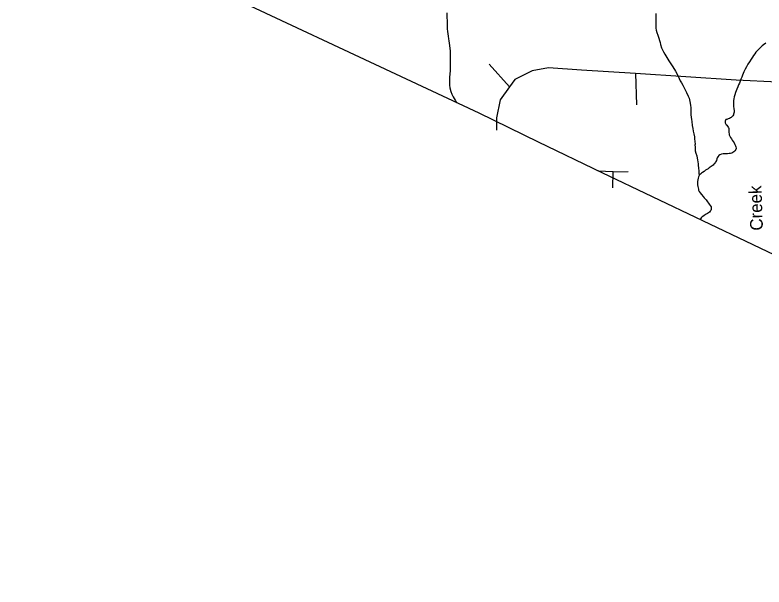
# Model space of a CAD drawing. Extents: x 2056842 to 2160602, y 826753 to 1016856.
# Drawn here: x 2109914 to 2115543, y 832817 to 837119 of the extents above; entities that cross this region are included whole.
import ezdxf

# ---------------------------------------------------------------- set-up
doc = ezdxf.new("R2010")
doc.units = 0
for name, color, linetype in [('Exist Boundary Political CountyLine', 7, 'Continuous'), ('Exist Hydrographic Misc Water Feature', 7, 'Continuous'), ('Exist Road Non-System Type 51', 7, 'Continuous'), ('Exist Road Non-System Type 51 Label', 7, 'Continuous')]:
    doc.layers.add(name, color=color, linetype=linetype)

msp = doc.modelspace()

# ---------------------------------------------------------------- linework, layer by layer
at = {"layer": 'Exist Boundary Political CountyLine'}
msp.add_lwpolyline([(2102162, 841868.8), (2110170.3, 837920.8), (2110936.9, 837538.4), (2113401.3, 836382.3), (2113845.4, 836165.5), (2114325.1, 835933.8), (2116216.5, 835032.6), (2117012.9, 834657.8), (2117168.3, 834572.5), (2123082.8, 831883.9), (2127502, 829978.1), (2130799, 828547.5), (2131147.1, 828402.1), (2131915.4, 828068), (2133839.4, 827270.1)], dxfattribs=at)
at = {"layer": 'Exist Hydrographic Misc Water Feature'}
for points in [[(2113158.5, 837134.1), (2113158.5, 837106.1), (2113161, 837067.6), (2113161.2, 837037.9), (2113163, 837014.1), (2113165.3, 836993.5), (2113170, 836958.3), (2113171.6, 836940.2), (2113173.9, 836923.6), (2113180.2, 836890.2), (2113182.7, 836866.3), (2113184.8, 836848.1), (2113184.8, 836828.2), (2113185, 836806.3), (2113184.8, 836789.7), (2113185.4, 836775.8), (2113185.6, 836768.5), (2113183.7, 836724.2), (2113183.5, 836700.6), (2113182.1, 836674.5), (2113180.6, 836652), (2113178.8, 836628.3), (2113178.8, 836608), (2113179.2, 836589.7), (2113183.1, 836570.1), (2113189.5, 836544.3), (2113197.7, 836522.4), (2113207.9, 836502.2), (2113222.1, 836478.1), (2113233, 836461.3), (2113237.3, 836459.2)], [(2114730, 837129.4), (2114730, 837104.2)], [(2114730, 837104.2), (2114730.2, 837081.9), (2114730.6, 837054.2), (2114731, 837035.9), (2114730.8, 837019.7), (2114732.9, 837003.9), (2114737, 836987.5), (2114745.2, 836966), (2114752, 836944.7), (2114757.3, 836926.4), (2114761.8, 836912.3), (2114765.9, 836895.9), (2114774.1, 836871.9), (2114788.5, 836842.2), (2114798.7, 836824.8), (2114812.9, 836798.3), (2114826.8, 836774.7), (2114843.2, 836750.7), (2114857.6, 836729.1), (2114877.7, 836696.8), (2114890, 836673.5), (2114906, 836639.8), (2114914.2, 836623.1), (2114922.6, 836607.2), (2114932.4, 836589.9), (2114948.8, 836559.9), (2114961.3, 836535.7), (2114973.2, 836507.9), (2114979.6, 836491.9), (2114985.5, 836467.4), (2114990, 836440), (2114992.3, 836420.6), (2114992.5, 836403.9), (2114994.1, 836385.8), (2114994.5, 836367.9), (2114998.6, 836331.6), (2115001.1, 836317.8), (2115003.6, 836286.6), (2115007.3, 836265.8), (2115011.6, 836246), (2115016.1, 836223.9), (2115020.2, 836202.6), (2115022, 836186), (2115023.2, 836168), (2115024.7, 836148.3), (2115024.3, 836138.6), (2115024.9, 836126), (2115024.7, 836112.2), (2115026.5, 836095.7), (2115031.2, 836080), (2115037.2, 836060.4), (2115041.5, 836042.3), (2115043.3, 836028.2), (2115045.6, 836014.1), (2115047.6, 835998.3), (2115048.5, 835985.2), (2115050.1, 835972), (2115051.1, 835962.5), (2115052.6, 835951), (2115053.8, 835937.8), (2115053.8, 835925.6), (2115054.8, 835910.5)], [(2115557.6, 836906.6), (2115539.8, 836893.9), (2115529.9, 836886.1), (2115520.7, 836878.6), (2115511.1, 836869.1), (2115498.4, 836856.4), (2115482.4, 836837.7), (2115473.7, 836826.4), (2115464.7, 836813.6), (2115456.9, 836801.4), (2115446.9, 836785.1), (2115435, 836767.4), (2115422.5, 836747.8), (2115411.2, 836729.2), (2115401.6, 836711.6), (2115391.7, 836691.1), (2115382.3, 836665), (2115376.1, 836650.5), (2115370, 836634.8), (2115364.7, 836620.2), (2115358.7, 836604.9), (2115352.8, 836592.8), (2115347, 836578.6), (2115338.8, 836560), (2115333.5, 836548.6), (2115328.8, 836535.6), (2115323, 836518.6), (2115318.9, 836503.8), (2115315.9, 836488.4), (2115314, 836474.5), (2115314, 836463.9), (2115313.8, 836445.7), (2115314, 836436), (2115315, 836426.9), (2115316.5, 836417.8), (2115317.3, 836410.3), (2115318.5, 836404.1), (2115318.7, 836395.5), (2115318.3, 836388.2), (2115316.5, 836380), (2115314.8, 836371.7), (2115312.8, 836367.2), (2115309.5, 836361.2), (2115304.8, 836355.8), (2115296.8, 836347.7), (2115291.5, 836344.4), (2115284.5, 836340.6), (2115275.1, 836337.6), (2115263, 836333.7), (2115257, 836331.4), (2115252.7, 836326.3), (2115250.2, 836319), (2115250.2, 836313.4), (2115251.3, 836307.5), (2115253.3, 836301.9), (2115255.6, 836299.2), (2115259.7, 836293.6), (2115263.6, 836289.4), (2115269.7, 836282.4), (2115273.8, 836276.1), (2115275.7, 836271.8), (2115277.7, 836263.8)], [(2115277.7, 836263.8), (2115279.6, 836254.5), (2115279.8, 836244), (2115280, 836234.2), (2115280.2, 836224.8), (2115281.8, 836217.7), (2115286.3, 836206), (2115290.4, 836197.7), (2115298.2, 836186), (2115304.6, 836177.7), (2115312.2, 836166.9), (2115318.7, 836156.1), (2115324.5, 836144.7), (2115329.2, 836134.6), (2115331.6, 836126.5), (2115333.3, 836118.2), (2115333.1, 836114.2), (2115331.2, 836105.9), (2115324.9, 836096.3), (2115317.3, 836088.2), (2115309.7, 836083.2), (2115301.5, 836080), (2115291.3, 836077.9), (2115280.4, 836075.9), (2115269.9, 836074.2), (2115257.8, 836073.6), (2115247.2, 836073.2), (2115235.3, 836073.4), (2115223.2, 836072), (2115211.3, 836067.3), (2115203.5, 836060.8), (2115195.5, 836051.4), (2115191.6, 836043.1), (2115189.5, 836036.5), (2115186.1, 836025.3), (2115182.2, 836016.9), (2115178.1, 836010.6), (2115173.8, 836004.8), (2115167, 835996.9), (2115162.1, 835990.4), (2115154.7, 835984.6), (2115146.5, 835978.5), (2115130.7, 835967.9), (2115122.5, 835962.6), (2115113.5, 835957.1), (2115104.2, 835950.4), (2115092.8, 835942), (2115080.9, 835934.1), (2115073.1, 835928.3), (2115065.1, 835921.8), (2115059.7, 835917), (2115054.8, 835910.5)], [(2115054.8, 835910.5), (2115050.7, 835901.7), (2115048.1, 835891.2), (2115044.8, 835878.7), (2115043.5, 835865.9), (2115043.5, 835853.3), (2115043.3, 835842), (2115045.6, 835829.5), (2115049.9, 835809.8), (2115052, 835801.7), (2115056.3, 835791.7), (2115064.1, 835780), (2115074.5, 835768.3), (2115086, 835753.9), (2115094.6, 835744.2), (2115102.2, 835735.7), (2115108.5, 835728.2), (2115119, 835714.1), (2115125.8, 835704.1), (2115131.9, 835695.1), (2115139.1, 835686.7), (2115145, 835676.5), (2115147.3, 835670), (2115147.3, 835662.7), (2115146.3, 835656), (2115142.8, 835648), (2115139.3, 835642.5), (2115133.8, 835636.8), (2115127.2, 835630.9), (2115119.6, 835626.4), (2115109.6, 835619.7), (2115093.6, 835610.4), (2115083.7, 835604.2), (2115075.7, 835597.7), (2115069.8, 835592.1), (2115063.8, 835581.8)]]:
    msp.add_lwpolyline(points, dxfattribs=at)
at = {"layer": 'Exist Road Non-System Type 51'}
for p, q in [((2113629.9, 836578.9), (2113478.3, 836749.3)), ((2114578.1, 836679.7), (2114584.3, 836442.8)), ((2114409.9, 835939.8), (2114293.6, 835943.9)), ((2114409.9, 835939.8), (2114522, 835941.8)), ((2114406.9, 835818.7), (2114409.9, 835939.8))]:
    msp.add_line(p, q, dxfattribs=at)
for points in [[(2114578.1, 836679.7), (2114171, 836702.6), (2113923.8, 836721.3), (2113801.3, 836698.4), (2113669.4, 836632.9), (2113629.9, 836578.9)], [(2115966.6, 836479.1), (2115819.1, 836566.4), (2115646.7, 836612.1), (2115333.1, 836628.8), (2114578.1, 836679.7)], [(2113629.9, 836578.9), (2113559.3, 836481.2), (2113532.3, 836346.1), (2113532.3, 836252.2)]]:
    msp.add_lwpolyline(points, dxfattribs=at)

# ---------------------------------------------------------------- texts
at = {"layer": 'Exist Road Non-System Type 51 Label'}
msp.add_text('Creek', height=95, rotation=91.9233, dxfattribs=at).set_placement((2115535.3, 835498.5))

doc.saveas('drawing.dxf')
